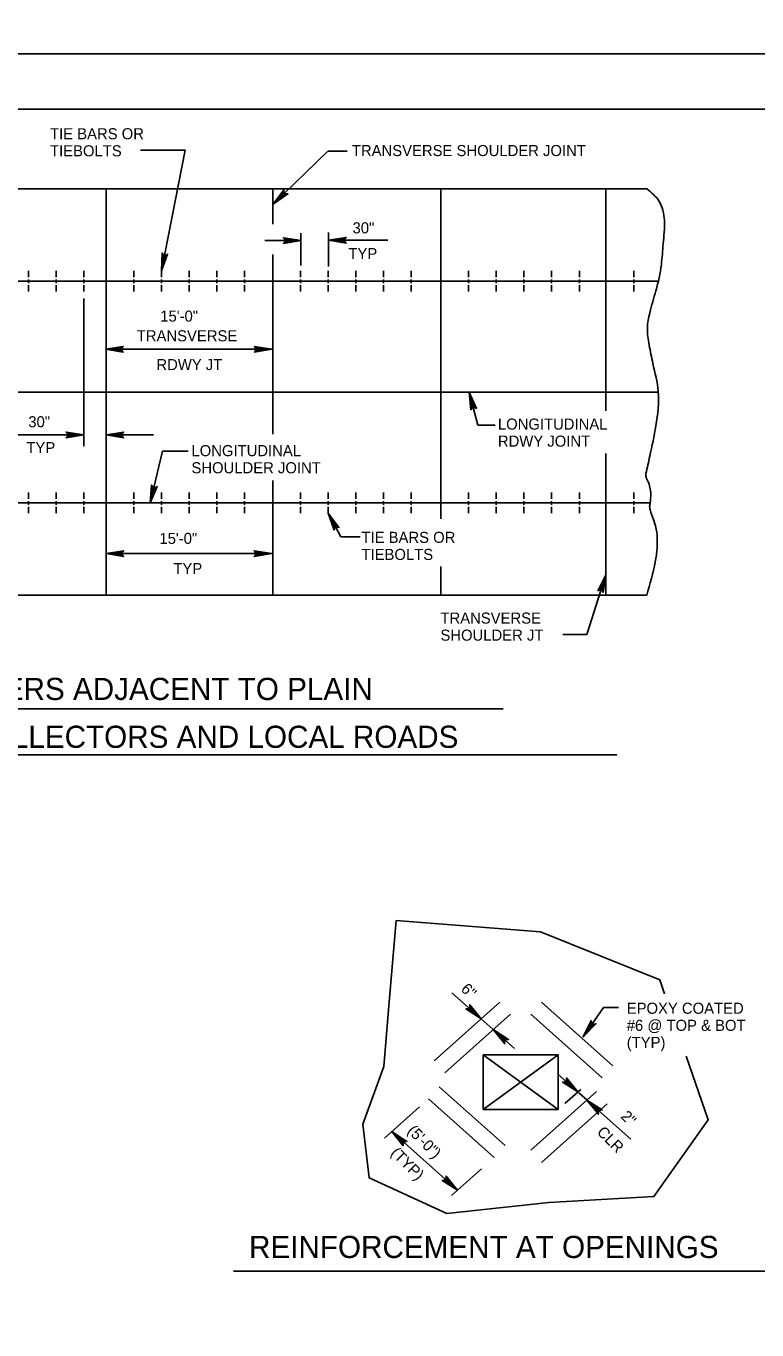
# Model space of a CAD drawing. Extents: x 638216 to 639962, y 297510 to 299292.
# Drawn here: x 638408.4 to 638606.1, y 297758.8 to 298111.7 of the extents above; entities that cross this region are included whole.
import ezdxf

# ---------------------------------------------------------------- set-up
doc = ezdxf.new("R2010")
doc.units = 0
for name, color, linetype in [('1', 7, 'Continuous'), ('2', 7, 'Continuous'), ('3', 7, 'Continuous'), ('PLT-BNDY', 7, 'Continuous')]:
    doc.layers.add(name, color=color, linetype=linetype)

msp = doc.modelspace()

# ---------------------------------------------------------------- linework, layer by layer
at = {"layer": '1'}
msp.add_lwpolyline([(639041.88, 297525.24), (639041.88, 298089.24), (638255.88, 298089.24), (638255.88, 297525.24), (639041.88, 297525.24), (639041.88, 297551.6), (638841.88, 297551.6), (638841.88, 297616.28), (639041.88, 297616.28), (639041.88, 297645.24), (638841.88, 297645.24), (638841.88, 297525.24), (638920.69, 297525.24), (638920.69, 297551.6), (638920.69, 297525.24), (638997.69, 297525.24), (638997.69, 297551.6), (638997.69, 297539.28), (639041.88, 297539.28)], dxfattribs=at)
msp.add_lwpolyline([(639041.88, 297525.24), (639041.88, 298089.24), (638255.88, 298089.24), (638255.88, 297525.24), (639041.88, 297525.24), (639041.88, 297551.6), (638841.88, 297551.6), (638841.88, 297616.28), (639041.88, 297616.28), (639041.88, 297645.24), (638841.88, 297645.24), (638841.88, 297525.24), (638920.69, 297525.24), (638920.69, 297551.6), (638920.69, 297525.24), (638997.69, 297525.24), (638997.69, 297551.6), (638997.69, 297539.28), (639041.88, 297539.28)], dxfattribs=at)
msp.add_lwpolyline([(639041.88, 297525.24), (639041.88, 298089.24), (638255.88, 298089.24), (638255.88, 297525.24), (639041.88, 297525.24), (639041.88, 297551.6), (638841.88, 297551.6), (638841.88, 297616.28), (639041.88, 297616.28), (639041.88, 297645.24), (638841.88, 297645.24), (638841.88, 297525.24), (638920.69, 297525.24), (638920.69, 297551.6), (638920.69, 297525.24), (638997.69, 297525.24), (638997.69, 297551.6), (638997.69, 297539.28), (639041.88, 297539.28)], dxfattribs=at)
at = {"layer": '2'}
for p, q in [((638439.3, 298078.16), (638451.4, 298078.16)), ((638451.4, 298078.16), (638445.01, 298045.49)), ((638489.97, 298077.76), (638475.24, 298063.57)), ((638490.06, 298077.84), (638495.23, 298077.84)), ((638276.33, 298067.68), (638576.33, 298067.68)), ((638430.01, 297957.68), (638430.01, 298067.68)), ((638475.11, 298058.11), (638475.11, 298067.68)), ((638520.59, 297978.36), (638520.59, 298067.68)), ((638565.29, 298007.57), (638565.29, 298067.68)), ((638482.69, 298046.9), (638482.69, 298055.72)), ((638490.24, 298046.69), (638490.24, 298055.84)), ((638472.98, 298053.69), (638482.79, 298053.69)), ((638490.24, 298053.75), (638506.29, 298053.75)), ((638475.11, 298001.3), (638475.11, 298049.91)), ((638408.99, 298043.79), (638408.99, 298045.49)), ((638416.49, 298043.79), (638416.49, 298045.49)), ((638423.99, 298043.79), (638423.99, 298045.49)), ((638437.51, 298043.79), (638437.51, 298045.49)), ((638445.01, 298043.79), (638445.01, 298045.49)), ((638452.51, 298043.79), (638452.51, 298045.49)), ((638460.01, 298043.79), (638460.01, 298045.49)), ((638467.51, 298043.79), (638467.51, 298045.49)), ((638482.61, 298043.79), (638482.61, 298045.49)), ((638490.11, 298043.79), (638490.11, 298045.49)), ((638497.61, 298043.79), (638497.61, 298045.49)), ((638505.11, 298043.79), (638505.11, 298045.49)), ((638512.61, 298043.79), (638512.61, 298045.49)), ((638528.09, 298043.79), (638528.09, 298045.49)), ((638535.59, 298043.79), (638535.59, 298045.49)), ((638543.09, 298043.79), (638543.09, 298045.49)), ((638550.59, 298043.79), (638550.59, 298045.49)), ((638558.09, 298043.79), (638558.09, 298045.49)), ((638572.79, 298043.79), (638572.79, 298045.49)), ((638279.72, 298042.68), (638579.3, 298042.68)), ((638408.99, 298042.18), (638408.99, 298043.15)), ((638408.99, 298039.87), (638408.99, 298041.64)), ((638416.49, 298042.18), (638416.49, 298043.15)), ((638416.49, 298039.87), (638416.49, 298041.64)), ((638423.99, 298042.18), (638423.99, 298043.15)), ((638423.99, 298039.87), (638423.99, 298041.64)), ((638437.51, 298042.18), (638437.51, 298043.15)), ((638437.51, 298039.87), (638437.51, 298041.64)), ((638445.01, 298042.18), (638445.01, 298043.15)), ((638445.01, 298039.87), (638445.01, 298041.64)), ((638452.51, 298042.18), (638452.51, 298043.15)), ((638452.51, 298039.87), (638452.51, 298041.64)), ((638460.01, 298042.18), (638460.01, 298043.15)), ((638460.01, 298039.87), (638460.01, 298041.64)), ((638467.51, 298042.18), (638467.51, 298043.15)), ((638467.51, 298039.87), (638467.51, 298041.64)), ((638482.61, 298042.18), (638482.61, 298043.15)), ((638482.61, 298039.87), (638482.61, 298041.64)), ((638490.11, 298042.18), (638490.11, 298043.15)), ((638490.11, 298039.87), (638490.11, 298041.64)), ((638497.61, 298042.18), (638497.61, 298043.15)), ((638497.61, 298039.87), (638497.61, 298041.64)), ((638505.11, 298042.18), (638505.11, 298043.15)), ((638505.11, 298039.87), (638505.11, 298041.64)), ((638512.61, 298042.18), (638512.61, 298043.15)), ((638512.61, 298039.87), (638512.61, 298041.64)), ((638528.09, 298042.18), (638528.09, 298043.15)), ((638528.09, 298039.87), (638528.09, 298041.64)), ((638535.59, 298042.18), (638535.59, 298043.15)), ((638535.59, 298039.87), (638535.59, 298041.64)), ((638543.09, 298042.18), (638543.09, 298043.15)), ((638543.09, 298039.87), (638543.09, 298041.64)), ((638550.59, 298042.18), (638550.59, 298043.15)), ((638550.59, 298039.87), (638550.59, 298041.64)), ((638558.09, 298042.18), (638558.09, 298043.15)), ((638558.09, 298039.87), (638558.09, 298041.64)), ((638572.79, 298042.18), (638572.79, 298043.15)), ((638572.79, 298039.87), (638572.79, 298041.64)), ((638423.99, 297998.02), (638423.99, 298037.99)), ((638429.91, 298024.26), (638474.9, 298024.26)), ((638317.13, 298012.68), (638579.51, 298012.68)), ((638530.66, 298003.68), (638528.25, 298012.68)), ((638530.66, 298003.68), (638535.27, 298003.68)), ((638406.14, 298001.07), (638423.99, 298001.07)), ((638430.01, 298001.07), (638442.88, 298001.07)), ((638445.26, 297996.66), (638441.99, 297982.68)), ((638445.26, 297996.66), (638452.25, 297996.66)), ((638565.29, 297957.68), (638565.29, 297996.01)), ((638475.11, 297957.68), (638475.11, 297988.75)), ((638408.99, 297983.79), (638408.99, 297985.49)), ((638416.49, 297983.79), (638416.49, 297985.49)), ((638423.99, 297983.79), (638423.99, 297985.49)), ((638437.51, 297983.79), (638437.51, 297985.49)), ((638445.01, 297983.79), (638445.01, 297985.49)), ((638452.51, 297983.79), (638452.51, 297985.49)), ((638460.01, 297983.79), (638460.01, 297985.49)), ((638467.51, 297983.79), (638467.51, 297985.49)), ((638482.61, 297983.79), (638482.61, 297985.49)), ((638490.11, 297983.79), (638490.11, 297985.49)), ((638497.61, 297983.79), (638497.61, 297985.49)), ((638505.11, 297983.79), (638505.11, 297985.49)), ((638512.61, 297983.79), (638512.61, 297985.49)), ((638528.09, 297983.79), (638528.09, 297985.49)), ((638535.59, 297983.79), (638535.59, 297985.49)), ((638543.09, 297983.79), (638543.09, 297985.49)), ((638550.59, 297983.79), (638550.59, 297985.49)), ((638558.09, 297983.79), (638558.09, 297985.49)), ((638572.79, 297983.79), (638572.79, 297985.49)), ((638272.76, 297982.68), (638577.2, 297982.68)), ((638276.33, 297982.68), (638576.33, 297982.68)), ((638408.99, 297982.18), (638408.99, 297983.15)), ((638408.99, 297979.87), (638408.99, 297981.64)), ((638416.49, 297982.18), (638416.49, 297983.15)), ((638416.49, 297979.87), (638416.49, 297981.64)), ((638423.99, 297982.18), (638423.99, 297983.15)), ((638423.99, 297979.87), (638423.99, 297981.64)), ((638437.51, 297982.18), (638437.51, 297983.15)), ((638437.51, 297979.87), (638437.51, 297981.64)), ((638445.01, 297982.18), (638445.01, 297983.15)), ((638445.01, 297979.87), (638445.01, 297981.64)), ((638452.51, 297982.18), (638452.51, 297983.15)), ((638452.51, 297979.87), (638452.51, 297981.64)), ((638460.01, 297982.18), (638460.01, 297983.15)), ((638460.01, 297979.87), (638460.01, 297981.64)), ((638467.51, 297982.18), (638467.51, 297983.15)), ((638467.51, 297979.87), (638467.51, 297981.64)), ((638482.61, 297982.18), (638482.61, 297983.15)), ((638482.61, 297979.87), (638482.61, 297981.64)), ((638490.11, 297982.18), (638490.11, 297983.15)), ((638490.11, 297979.87), (638490.11, 297981.64)), ((638497.61, 297982.18), (638497.61, 297983.15)), ((638497.61, 297979.87), (638497.61, 297981.64)), ((638505.11, 297982.18), (638505.11, 297983.15)), ((638505.11, 297979.87), (638505.11, 297981.64)), ((638512.61, 297982.18), (638512.61, 297983.15)), ((638512.61, 297979.87), (638512.61, 297981.64)), ((638528.09, 297982.18), (638528.09, 297983.15)), ((638528.09, 297979.87), (638528.09, 297981.64)), ((638535.59, 297982.18), (638535.59, 297983.15)), ((638535.59, 297979.87), (638535.59, 297981.64)), ((638543.09, 297982.18), (638543.09, 297983.15)), ((638543.09, 297979.87), (638543.09, 297981.64)), ((638550.59, 297982.18), (638550.59, 297983.15)), ((638550.59, 297979.87), (638550.59, 297981.64)), ((638558.09, 297982.18), (638558.09, 297983.15)), ((638558.09, 297979.87), (638558.09, 297981.64)), ((638572.79, 297982.18), (638572.79, 297983.15)), ((638572.79, 297979.87), (638572.79, 297981.64)), ((638493.58, 297973.47), (638490.11, 297979.87)), ((638493.58, 297973.47), (638498.8, 297973.47)), ((638430.01, 297968.94), (638474.85, 297968.94)), ((638520.59, 297957.68), (638520.59, 297965.42)), ((638560.12, 297947.05), (638565.29, 297963.22)), ((638276.4, 297957.68), (638576.33, 297957.68)), ((638553.66, 297947.05), (638560.12, 297947.05)), ((638318.87, 297926.94), (638537.44, 297926.94)), ((638276.14, 297914.52), (638568.21, 297914.52)), ((638523.62, 297850.08), (638531.52, 297843.04)), ((638518.77, 297831.67), (638536.57, 297847.55)), ((638567.15, 297830.34), (638547.86, 297847.55)), ((638521.69, 297828.39), (638539.49, 297844.27)), ((638531.52, 297843.04), (638534.81, 297840.1)), ((638564.22, 297827.06), (638544.93, 297844.27)), ((638564.65, 297846.09), (638559.15, 297838.13)), ((638564.65, 297846.09), (638568.7, 297846.09)), ((638534.81, 297840.1), (638540.53, 297835)), ((638532.07, 297818.48), (638552.35, 297833.24)), ((638532.07, 297833.24), (638552.35, 297818.48)), ((638552.2, 297828.12), (638557.68, 297823.23)), ((638520.2, 297824.66), (638537.99, 297808.78)), ((638562.73, 297823.33), (638544.93, 297807.45)), ((638558.45, 297823.92), (638554.15, 297820.08)), ((638557.91, 297823.03), (638560.08, 297821.09)), ((638514.81, 297819.18), (638505.36, 297810.76)), ((638517.27, 297821.39), (638535.07, 297805.51)), ((638565.65, 297820.05), (638547.86, 297804.18)), ((638560.15, 297821.03), (638571.99, 297810.47)), ((638507.32, 297812.5), (638525.11, 297796.63)), ((638531.65, 297802.45), (638523.49, 297795.18)), ((638464.47, 297774.7), (638616.64, 297774.7))]:
    msp.add_line(p, q, dxfattribs=at)
for points in [[(638478.91, 298066.3), (638478.56, 298066.43), (638475.24, 298063.57), (638478.91, 298066.3), (638479.21, 298066.32), (638475.24, 298063.57), (638478.24, 298066.75), (638478.13, 298067.1), (638475.24, 298063.57), (638478.15, 298067.42), (638478.13, 298067.1)], [(638494.78, 298053.18), (638494.61, 298053.51), (638490.24, 298053.75), (638494.78, 298053.18), (638495.01, 298052.98), (638490.24, 298053.75), (638494.61, 298053.97), (638494.76, 298054.29), (638490.24, 298053.75), (638495.01, 298054.51), (638494.76, 298054.29)], [(638478.25, 298054.26), (638478.42, 298053.93), (638482.79, 298053.69), (638478.25, 298054.26), (638478.02, 298054.46), (638482.79, 298053.69), (638478.43, 298053.47), (638478.27, 298053.15), (638482.79, 298053.69), (638478.02, 298052.93), (638478.27, 298053.15)], [(638446.44, 298049.84), (638446.09, 298049.74), (638445.01, 298045.49), (638446.44, 298049.84), (638446.68, 298050.03), (638445.01, 298045.49), (638445.64, 298049.82), (638445.35, 298050.04), (638445.01, 298045.49), (638445.19, 298050.33), (638445.35, 298050.04)], [(638434.45, 298023.69), (638434.28, 298024.02), (638429.91, 298024.26), (638434.45, 298023.69), (638434.68, 298023.49), (638429.91, 298024.26), (638434.28, 298024.48), (638434.44, 298024.8), (638429.91, 298024.26), (638434.68, 298025.02), (638434.44, 298024.8)], [(638470.36, 298024.83), (638470.53, 298024.5), (638474.9, 298024.26), (638470.36, 298024.83), (638470.13, 298025.03), (638474.9, 298024.26), (638470.54, 298024.04), (638470.38, 298023.72), (638474.9, 298024.26), (638470.13, 298023.5), (638470.38, 298023.72)], [(638528.87, 298008.15), (638529.15, 298008.4), (638528.25, 298012.68), (638528.87, 298008.15), (638528.74, 298007.87), (638528.25, 298012.68), (638529.59, 298008.52), (638529.94, 298008.45), (638528.25, 298012.68), (638530.22, 298008.27), (638529.94, 298008.45)], [(638419.45, 298001.64), (638419.62, 298001.31), (638423.99, 298001.07), (638419.45, 298001.64), (638419.22, 298001.84), (638423.99, 298001.07), (638419.62, 298000.85), (638419.46, 298000.53), (638423.99, 298001.07), (638419.22, 298000.31), (638419.46, 298000.53)], [(638434.56, 298000.5), (638434.39, 298000.83), (638430.01, 298001.07), (638434.56, 298000.5), (638434.79, 298000.3), (638430.01, 298001.07), (638434.38, 298001.29), (638434.54, 298001.61), (638430.01, 298001.07), (638434.79, 298001.83), (638434.54, 298001.61)], [(638443.58, 297986.97), (638443.22, 297986.88), (638441.99, 297982.68), (638443.58, 297986.97), (638443.83, 297987.15), (638441.99, 297982.68), (638442.77, 297986.98), (638442.5, 297987.21), (638441.99, 297982.68), (638442.34, 297987.5), (638442.5, 297987.21)], [(638491.77, 297975.61), (638491.98, 297975.91), (638490.11, 297979.87), (638491.77, 297975.61), (638491.71, 297975.31), (638490.11, 297979.87), (638492.38, 297976.13), (638492.74, 297976.15), (638490.11, 297979.87), (638493.05, 297976.04), (638492.74, 297976.15)], [(638434.55, 297968.37), (638434.39, 297968.7), (638430.01, 297968.94), (638434.55, 297968.37), (638434.79, 297968.17), (638430.01, 297968.94), (638434.38, 297969.15), (638434.54, 297969.48), (638430.01, 297968.94), (638434.79, 297969.7), (638434.54, 297969.48)], [(638470.31, 297969.51), (638470.48, 297969.18), (638474.85, 297968.94), (638470.31, 297969.51), (638470.08, 297969.71), (638474.85, 297968.94), (638470.49, 297968.72), (638470.33, 297968.4), (638474.85, 297968.94), (638470.08, 297968.18), (638470.33, 297968.4)], [(638564.44, 297958.72), (638564.18, 297958.98), (638565.29, 297963.22), (638564.44, 297958.72), (638564.56, 297958.44), (638565.29, 297963.22), (638563.75, 297959.13), (638563.39, 297959.07), (638565.29, 297963.22), (638563.11, 297958.91), (638563.39, 297959.07)], [(638587, 297832.94), (638592.97, 297815.71), (638578.28, 297794.97), (638549.85, 297793.3), (638522.24, 297790.29), (638501.21, 297800.03), (638499.52, 297814.52), (638505.16, 297830.1), (638506.57, 297846.5), (638508.54, 297869.66), (638547.57, 297866.54), (638579.83, 297853.61), (638581.14, 297849.81)], [(638528.46, 297846.54), (638528.36, 297846.18), (638531.52, 297843.04), (638528.46, 297846.54), (638528.42, 297846.85), (638531.52, 297843.04), (638528.06, 297845.83), (638527.72, 297845.69), (638531.52, 297843.04), (638527.38, 297845.69), (638527.72, 297845.69)], [(638537.87, 297836.6), (638537.96, 297836.96), (638534.81, 297840.1), (638537.87, 297836.6), (638537.91, 297836.29), (638534.81, 297840.1), (638538.27, 297837.31), (638538.61, 297837.45), (638534.81, 297840.1), (638538.95, 297837.45), (638538.61, 297837.45)], [(638562.25, 297841.6), (638561.88, 297841.65), (638559.15, 297838.13), (638562.25, 297841.6), (638562.55, 297841.68), (638559.15, 297838.13), (638561.49, 297841.91), (638561.31, 297842.23), (638559.15, 297838.13), (638561.27, 297842.56), (638561.31, 297842.23)], [(638554.63, 297826.74), (638554.53, 297826.37), (638557.68, 297823.23), (638554.63, 297826.74), (638554.58, 297827.05), (638557.68, 297823.23), (638554.23, 297826.02), (638553.88, 297825.89), (638557.68, 297823.23), (638553.55, 297825.89), (638553.88, 297825.89)], [(638563.21, 297817.53), (638563.3, 297817.89), (638560.15, 297821.03), (638563.21, 297817.53), (638563.25, 297817.22), (638560.15, 297821.03), (638563.61, 297818.24), (638563.95, 297818.38), (638560.15, 297821.03), (638564.29, 297818.38), (638563.95, 297818.38)], [(638510.37, 297809), (638510.47, 297809.36), (638507.32, 297812.5), (638510.37, 297809), (638510.42, 297808.69), (638507.32, 297812.5), (638510.77, 297809.71), (638511.11, 297809.85), (638507.32, 297812.5), (638511.45, 297809.85), (638511.11, 297809.85)], [(638522.06, 297800.13), (638521.96, 297799.77), (638525.11, 297796.63), (638522.06, 297800.13), (638522.02, 297800.44), (638525.11, 297796.63), (638521.66, 297799.42), (638521.32, 297799.28), (638525.11, 297796.63), (638520.98, 297799.28), (638521.32, 297799.28)]]:
    msp.add_lwpolyline(points, dxfattribs=at)
msp.add_lwpolyline([(638532.07, 297818.48), (638552.35, 297818.48), (638552.35, 297833.24), (638532.07, 297833.24)], close=True, dxfattribs=at)
for points in [[(638576.33, 298067.68), (638579.61, 298064.4), (638581.1, 298059.1), (638580.77, 298052.82), (638580.28, 298047.2), (638578.79, 298040.09), (638577.15, 298034.16), (638576.49, 298030.03), (638576.99, 298025.4), (638577.98, 298020.44), (638579.45, 298012.83), (638578.79, 298003.57), (638577.15, 297995.3), (638576.1, 297990.62)], [(638576.1, 297990.62), (638576.16, 297989.66), (638576.78, 297988.21), (638577.28, 297986.35), (638577.44, 297985.2), (638577.32, 297983.67), (638577.28, 297982.8), (638577.11, 297981.68), (638577.36, 297980.48), (638577.58, 297979.66)], [(638577.58, 297979.66), (638578.46, 297977.28), (638579.12, 297970.36), (638578.62, 297966.72), (638576.33, 297957.68)]]:
    msp.add_spline(points, degree=3, dxfattribs=at)
at = {"layer": 'PLT-BNDY'}
for points in [[(638215.88, 298698.24), (639056.88, 298698.24), (639056.88, 298104.24), (638215.88, 298104.24)], [(638215.88, 298104.24), (639056.88, 298104.24), (639056.88, 297510.24), (638215.88, 297510.24)]]:
    msp.add_lwpolyline(points, close=True, dxfattribs=at)

# ---------------------------------------------------------------- texts
at = {"layer": '3'}
for s, height, p in [('TIE BARS OR', 3, (638414.86, 298081.1)), ('TIEBOLTS', 3, (638414.86, 298076.48)), ('TRANSVERSE SHOULDER JOINT', 3, (638496.54, 298076.55)), ('30"', 3, (638496.72, 298055.63)), ('TYP', 3, (638495.59, 298048.66)), ('15\'-0"', 3, (638444.69, 298031.73)), ('TRANSVERSE', 3, (638438.33, 298026.41)), ('RDWY JT', 3, (638443.64, 298018.62)), ('30"', 3, (638408.98, 298003.14)), ('LONGITUDINAL', 3, (638536.05, 298002.51)), ('TYP', 3, (638408.45, 297996.14)), ('LONGITUDINAL', 3, (638453.13, 297995.32)), ('RDWY JOINT', 3, (638536.05, 297997.89)), ('SHOULDER JOINT', 3, (638453.13, 297990.69)), ('15\'-0"', 3, (638444.46, 297971.57)), ('TIE BARS OR', 3, (638499.13, 297971.85)), ('TIEBOLTS', 3, (638499.13, 297967.23)), ('TYP', 3, (638448.23, 297963.41)), ('TRANSVERSE', 3, (638520.5, 297950)), ('SHOULDER JT', 3, (638520.5, 297945.38)), ('CONCRETE SHOULDERS ADJACENT TO PLAIN ', 6, (638321.65, 297929.32)), ('CONCRETE PAVEMENT FOR COLLECTORS AND LOCAL ROADS', 6, (638279.71, 297916.37)), ('EPOXY COATED', 3, (638570.91, 297844.39)), ('#6 @ TOP & BOT', 3, (638570.91, 297839.77)), ('(TYP)', 3, (638570.91, 297835.14)), ('REINFORCEMENT AT OPENINGS', 6, (638468.71, 297778.28))]:
    msp.add_text(s, height=height, dxfattribs=at).set_placement(p)
for s, p in [('6"', (638525.83, 297850.88)), ('2"', (638569.06, 297816.4)), ('(5\'-0")', (638511.35, 297812.5)), ('CLR', (638562.64, 297812.15)), ('(TYP)', (638506.85, 297806.49))]:
    msp.add_text(s, height=3, rotation=315, dxfattribs=at).set_placement(p)

doc.saveas('drawing.dxf')
